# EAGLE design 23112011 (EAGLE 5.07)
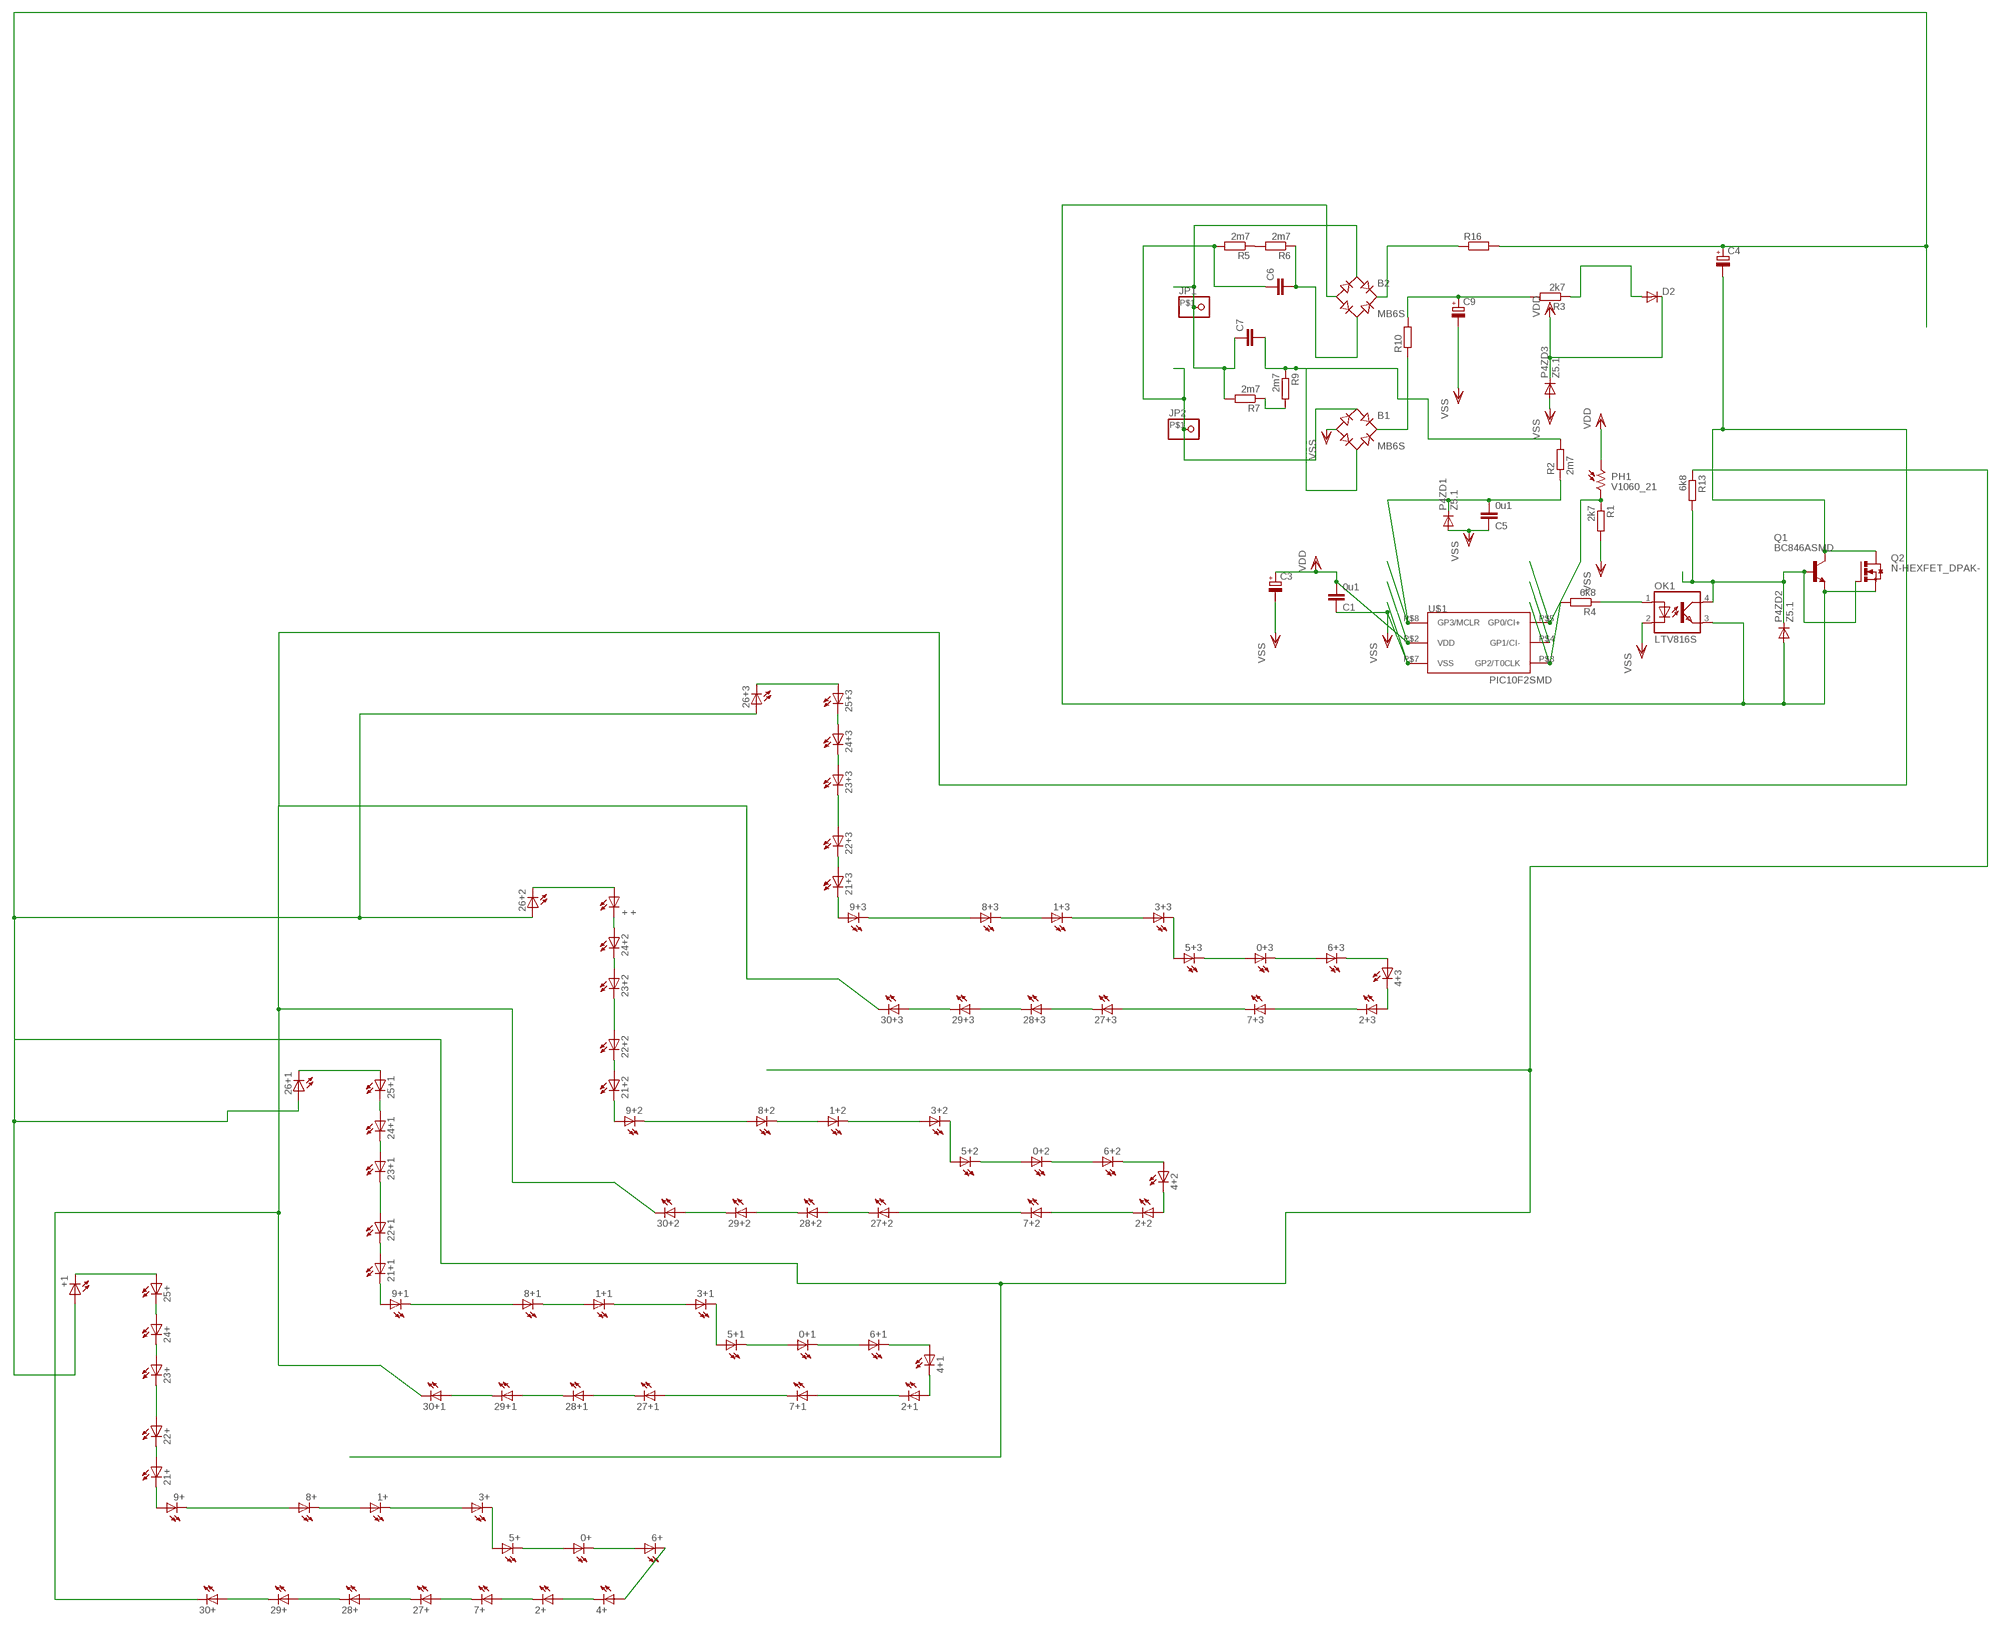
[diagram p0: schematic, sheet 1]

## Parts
0+  LED1210  [1210]
0+1  LED1210  [1210]
0+2  LED1210  [1210]
0+3  LED1210  [1210]
1+  LED1210  [1210]
1+1  LED1210  [1210]
1+2  LED1210  [1210]
1+3  LED1210  [1210]
2+  LED1210  [1210]
2+1  LED1210  [1210]
2+2  LED1210  [1210]
2+3  LED1210  [1210]
3+  LED1210  [1210]
3+1  LED1210  [1210]
3+2  LED1210  [1210]
3+3  LED1210  [1210]
4+  LED1210  [1210]
4+1  LED1210  [1210]
4+2  LED1210  [1210]
4+3  LED1210  [1210]
5+  LED1210  [1210]
5+1  LED1210  [1210]
5+2  LED1210  [1210]
5+3  LED1210  [1210]
6+  LED1210  [1210]
6+1  LED1210  [1210]
6+2  LED1210  [1210]
6+3  LED1210  [1210]
7+  LED1210  [1210]
7+1  LED1210  [1210]
7+2  LED1210  [1210]
7+3  LED1210  [1210]
8+  LED1210  [1210]
8+1  LED1210  [1210]
8+2  LED1210  [1210]
8+3  LED1210  [1210]
9+  LED1210  [1210]
9+1  LED1210  [1210]
9+2  LED1210  [1210]
9+3  LED1210  [1210]
21+  LED1210  [1210]
21+1  LED1210  [1210]
21+2  LED1210  [1210]
21+3  LED1210  [1210]
22+  LED1210  [1210]
22+1  LED1210  [1210]
22+2  LED1210  [1210]
22+3  LED1210  [1210]
23+  LED1210  [1210]
23+1  LED1210  [1210]
23+2  LED1210  [1210]
23+3  LED1210  [1210]
24+  LED1210  [1210]
24+1  LED1210  [1210]
24+2  LED1210  [1210]
24+3  LED1210  [1210]
25+  LED1210  [1210]
25+1  LED1210  [1210]
25+3  LED1210  [1210]
26+1  LED1210  [1210]
26+2  LED1210  [1210]
26+3  LED1210  [1210]
27+  LED1210  [1210]
27+1  LED1210  [1210]
27+2  LED1210  [1210]
27+3  LED1210  [1210]
28+  LED1210  [1210]
28+1  LED1210  [1210]
28+2  LED1210  [1210]
28+3  LED1210  [1210]
29+  LED1210  [1210]
29+1  LED1210  [1210]
29+2  LED1210  [1210]
29+3  LED1210  [1210]
30+  LED1210  [1210]
30+1  LED1210  [1210]
30+2  LED1210  [1210]
30+3  LED1210  [1210]
+  +  LED1210  [1210]
+1  LED1210  [1210]
B1  MB6S  [SOIC-4]
B2  MB6S  [SOIC-4]
C1  0u1  C-EUC1206  [C1206]
C3  CPOL-EUD  [PANASONIC_D]
C4  CPOL-EUSANYO_SMD_F12  [SANYO-OSCON_SMD_F12]
C5  0u1  C-EUC1206  [C1206]
C6  C-EUSMD200  [SMD200]
C7  C-EUSMD100  [SMD100]
C9  CPOL-EUD  [PANASONIC_D]
D2  DIODE-MINIMELF  [MINIMELF]
JP1  PINHD-1X1SMD  [SMD1X1]
JP2  PINHD-1X1SMD  [SMD1X1]
OK1  LTV816S  [SMD4]
P4ZD1  Z5.1  DIODE-MINIMELF  [MINIMELF]
P4ZD2  Z5.1  DIODE-MINIMELF  [MINIMELF]
P4ZD3  Z5.1  DIODE-MINIMELF  [MINIMELF]
PH1  V1060_21  [TO-5_V10]
Q1  BC846ASMD  [SOT23]
Q2  N-HEXFET_DPAK-  [TO252]
R1  2k7  R-EU_R1206  [R1206]
R2  2m7  R-EU_R1206  [R1206]
R3  2k7  R-EU_R1206  [R1206]
R4  6k8  R-EU_R1206  [R1206]
R5  2m7  R-EU_R1210  [R1210]
R6  2m7  R-EU_R1210  [R1210]
R7  2m7  R-EU_R1210  [R1210]
R9  2m7  R-EU_R1210  [R1210]
R10  R-EU_SMD15  [SMDCARB15]
R13  6k8  R-EU_R1206  [R1206]
R16  R-EU_SMD15  [SMDCARB15]
U$1  PIC10F2SMD  [DIL8SMD]

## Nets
AC1: B1.~1(AC1) C6.P$1 JP2.P$1 R5.2
AC2: B2.~1(AC1) C7.P$1 JP1.P$1 R7.2
CBIG: B2.~2(AC2) C6.P$2 R6.1
CSMALL: B1.~2(AC2) C7.P$2 R2.2 R9.1
D+: 26+1.P$1(A) 26+2.P$1(A) 26+3.P$1(A) +1.P$1(A) C4.+ R13.1 R16.P$2
DR+: C9.+ R3.2 R10.P$2
MINUS: 30+1.P$2(C) 30+2.P$2(C) 30+3.P$2(C) 30+.P$2(C) C4.- Q1.3(C) Q2.3(D)
N$6: 8+.P$1(A) 9+.P$2(C)
N$7: 29+.P$2(C) 30+.P$1(A)
N$8: 28+.P$2(C) 29+.P$1(A)
N$9: 27+.P$2(C) 28+.P$1(A)
N$10: 29+1.P$2(C) 30+1.P$1(A)
N$11: 28+1.P$2(C) 29+1.P$1(A)
N$12: 2+.P$2(C) 7+.P$1(A)
N$13: 7+.P$2(C) 27+.P$1(A)
N$14: 2+.P$1(A) 4+.P$2(C)
N$15: 4+.P$1(A) 6+.P$2(C)
N$16: 0+.P$2(C) 6+.P$1(A)
N$17: 0+.P$1(A) 5+.P$2(C)
N$18: 3+.P$2(C) 5+.P$1(A)
N$19: 1+.P$2(C) 3+.P$1(A)
N$20: 1+.P$1(A) 8+.P$2(C)
N$21: 27+1.P$2(C) 28+1.P$1(A)
N$22: 2+1.P$1(A) 4+1.P$2(C)
N$23: 9+.P$1(A) 21+.P$2(C)
N$24: 21+.P$1(A) 22+.P$2(C)
N$25: 22+.P$1(A) 23+.P$2(C)
N$26: 24+.P$1(A) 25+.P$2(C)
N$27: 25+.P$1(A) +1.P$2(C)
N$28: 23+.P$1(A) 24+.P$2(C)
N$29: 4+1.P$1(A) 6+1.P$2(C)
N$30: 0+1.P$2(C) 6+1.P$1(A)
N$31: 0+1.P$1(A) 5+1.P$2(C)
N$32: 3+1.P$2(C) 5+1.P$1(A)
N$33: 1+1.P$2(C) 3+1.P$1(A)
N$34: 1+1.P$1(A) 8+1.P$2(C)
N$35: 9+1.P$1(A) 21+1.P$2(C)
N$36: 21+1.P$1(A) 22+1.P$2(C)
N$37: 22+1.P$1(A) 23+1.P$2(C)
N$38: 25+1.P$1(A) 26+1.P$2(C)
N$39: 24+1.P$1(A) 25+1.P$2(C)
N$40: 23+1.P$1(A) 24+1.P$2(C)
N$41: 2+1.P$2(C) 7+1.P$1(A)
N$42: 7+1.P$2(C) 27+1.P$1(A)
N$43: 8+1.P$1(A) 9+1.P$2(C)
N$46: 29+2.P$2(C) 30+2.P$1(A)
N$47: 28+2.P$2(C) 29+2.P$1(A)
N$48: 27+2.P$2(C) 28+2.P$1(A)
N$49: 2+2.P$1(A) 4+2.P$2(C)
N$50: 4+2.P$1(A) 6+2.P$2(C)
N$51: 0+2.P$2(C) 6+2.P$1(A)
N$52: 0+2.P$1(A) 5+2.P$2(C)
N$53: 3+2.P$2(C) 5+2.P$1(A)
N$54: 1+2.P$2(C) 3+2.P$1(A)
N$55: 1+2.P$1(A) 8+2.P$2(C)
N$56: 9+2.P$1(A) 21+2.P$2(C)
N$57: 21+2.P$1(A) 22+2.P$2(C)
N$58: 22+2.P$1(A) 23+2.P$2(C)
N$59: 26+2.P$2(C) +.P$1(A)
N$60: 24+2.P$1(A) +.P$2(C)
N$61: 23+2.P$1(A) 24+2.P$2(C)
N$62: 2+2.P$2(C) 7+2.P$1(A)
N$63: 7+2.P$2(C) 27+2.P$1(A)
N$64: 8+2.P$1(A) 9+2.P$2(C)
N$67: 29+3.P$2(C) 30+3.P$1(A)
N$68: 28+3.P$2(C) 29+3.P$1(A)
N$69: 27+3.P$2(C) 28+3.P$1(A)
N$70: 2+3.P$1(A) 4+3.P$2(C)
N$71: 4+3.P$1(A) 6+3.P$2(C)
N$72: 0+3.P$2(C) 6+3.P$1(A)
N$73: 0+3.P$1(A) 5+3.P$2(C)
N$74: 3+3.P$2(C) 5+3.P$1(A)
N$75: 1+3.P$2(C) 3+3.P$1(A)
N$76: 1+3.P$1(A) 8+3.P$2(C)
N$77: 9+3.P$1(A) 21+3.P$2(C)
N$78: 21+3.P$1(A) 22+3.P$2(C)
N$79: 22+3.P$1(A) 23+3.P$2(C)
N$80: 25+3.P$1(A) 26+3.P$2(C)
N$81: 24+3.P$1(A) 25+3.P$2(C)
N$82: 23+3.P$1(A) 24+3.P$2(C)
N$83: 2+3.P$2(C) 7+3.P$1(A)
N$84: 7+3.P$2(C) 27+3.P$1(A)
N$85: 8+3.P$1(A) 9+3.P$2(C)
N$86: C5.2 P4ZD1.C R2.1 U$1.P$8(GP3/MCLR)
N$87: OK1.1(A) R4.1
N$88: PH1.2 R1.1 U$1.P$5(GP0/CI+)
N$89: R5.1 R6.2
N$90: R7.1 R9.2
N$91: B2.+ R16.P$1
N$92: D2.A R3.1
N$93: B2.- OK1.3(EMIT) P4ZD2.A Q1.2(E) Q2.2(S)
N$94: OK1.4(COL) P4ZD2.C Q1.1(B) Q2.1(G) R13.2
N$95: R4.2 U$1.P$3(GP2/T0CLK)
N$102: U$1.P$4(GP1/CI-)
RECDR+: B1.+ R10.P$1
VDD: C1.2 C3.+ D2.C P4ZD3.C PH1.1 U$1.P$2(VDD)
VSS: B1.- C1.1 C3.- C5.1 C9.- OK1.2(C) P4ZD1.A P4ZD3.A R1.2 U$1.P$7(VSS)

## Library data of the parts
0+ 0+1-0+3 1+ 1+1-1+3 2+ 2+1-2+3 3+ 3+1-3+3 4+ 4+1-4+3 5+ 5+1-5+3 6+ 6+1-6+3 7+ 7+1-7+3 8+ 8+1-8+3 9+ 9+1-9+3 21+ 21+1-21+3 22+ 22+1-22+3 23+ 23+1-23+3 24+ 24+1-24+3 25+ 25+1 25+3 26+1-26+3 27+ 27+1-27+3 28+ 28+1-28+3 29+ 29+1-29+3 30+ 30+1-30+3 + +1 = led(2):LED: LED
B1 B2 = rectifier:MB*S: Bridge Rectifier Source: http://www.fairchildsemi.com/ds/MB/MB6S.pdf
C1 C5-C7 = rcl:C-EU: CAPACITOR, European symbol
C3 C4 C9 = rcl-2:CPOL-EU: POLARIZED CAPACITOR, European symbol
D2 P4ZD1-P4ZD3 = diode:DIODE-: DIODE
JP1 JP2 = pinhead:PINHD-1X1: PIN HEADER
OK1 = optocoupler:LTV816: OPTO COUPLER Source: LITEON, LTV816.pdf
PH1 = photo-elements:?1060*: Sensor Street Light control
Q1 = transistor-npn:BC846*: NPN Transistor
Q2 = transistor-power:N-HEXFET_?-*: HEXFET® Power MOSFET
R1-R7 R9 R13 = rcl-2:R-EU_: RESISTOR, European symbol
R10 R16 = rcl:R-EU_: RESISTOR, European symbol
U$1 = microchip-5:PIC10F2*: uPC nW 0,25/0,5k Program Flash memory Comparator

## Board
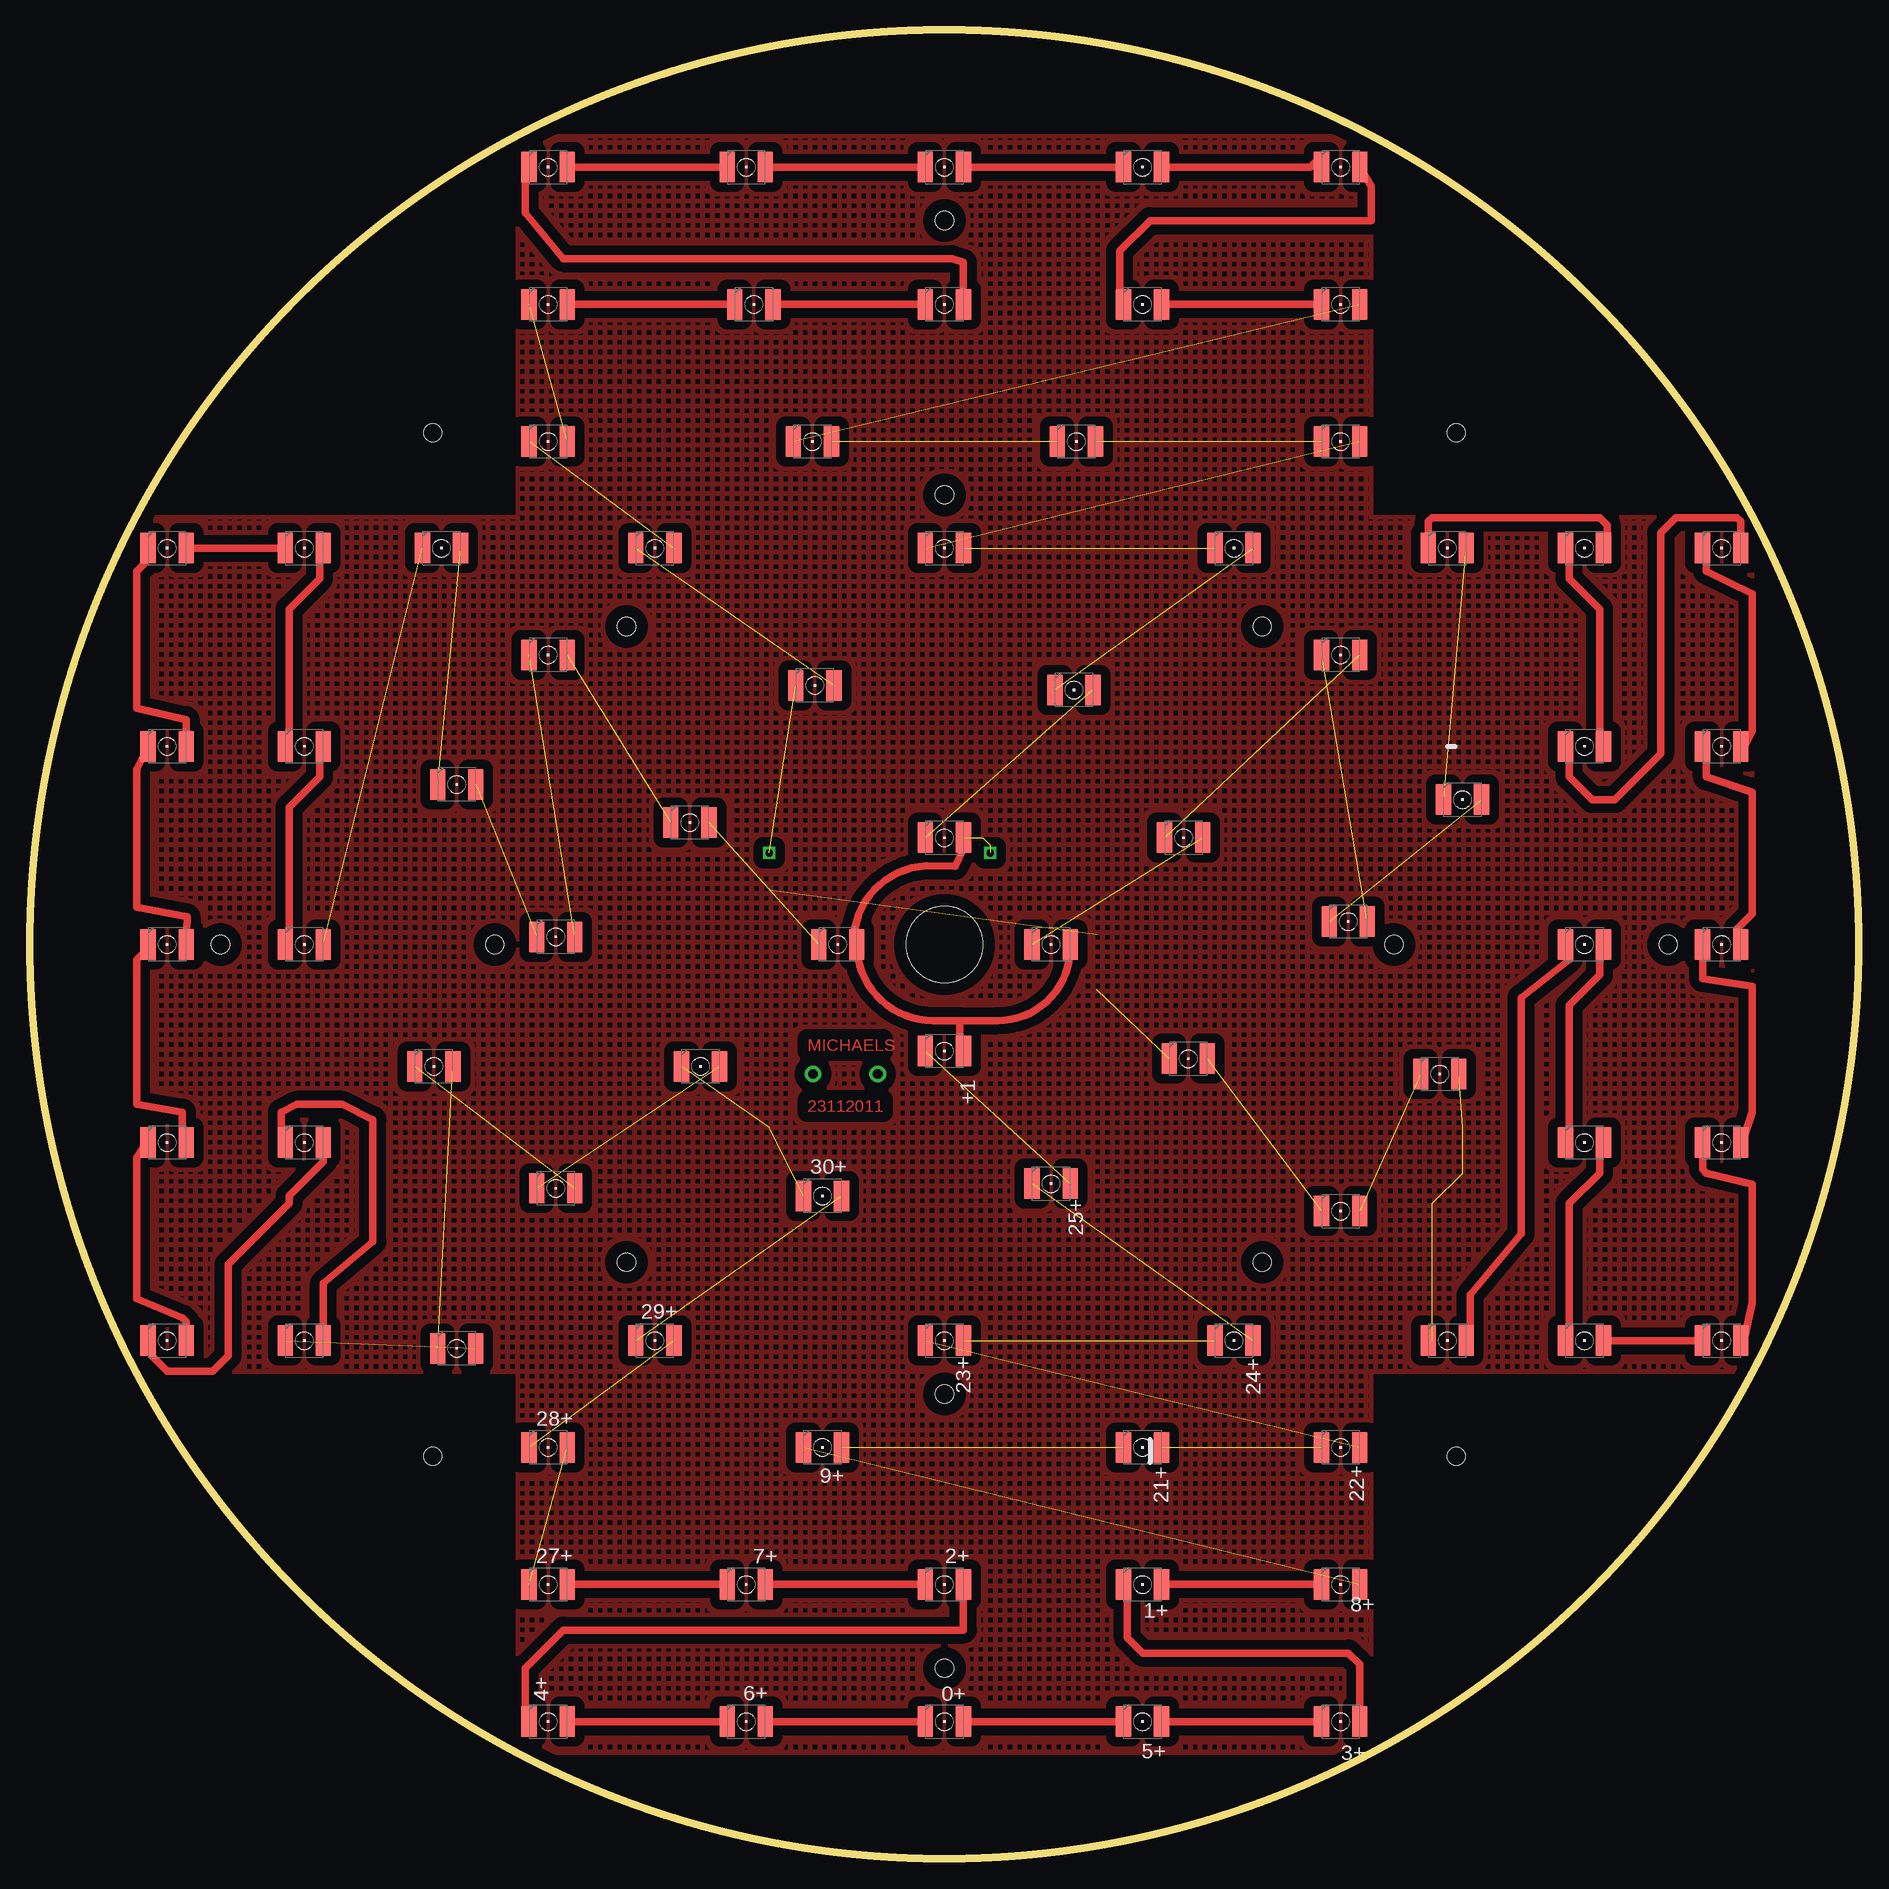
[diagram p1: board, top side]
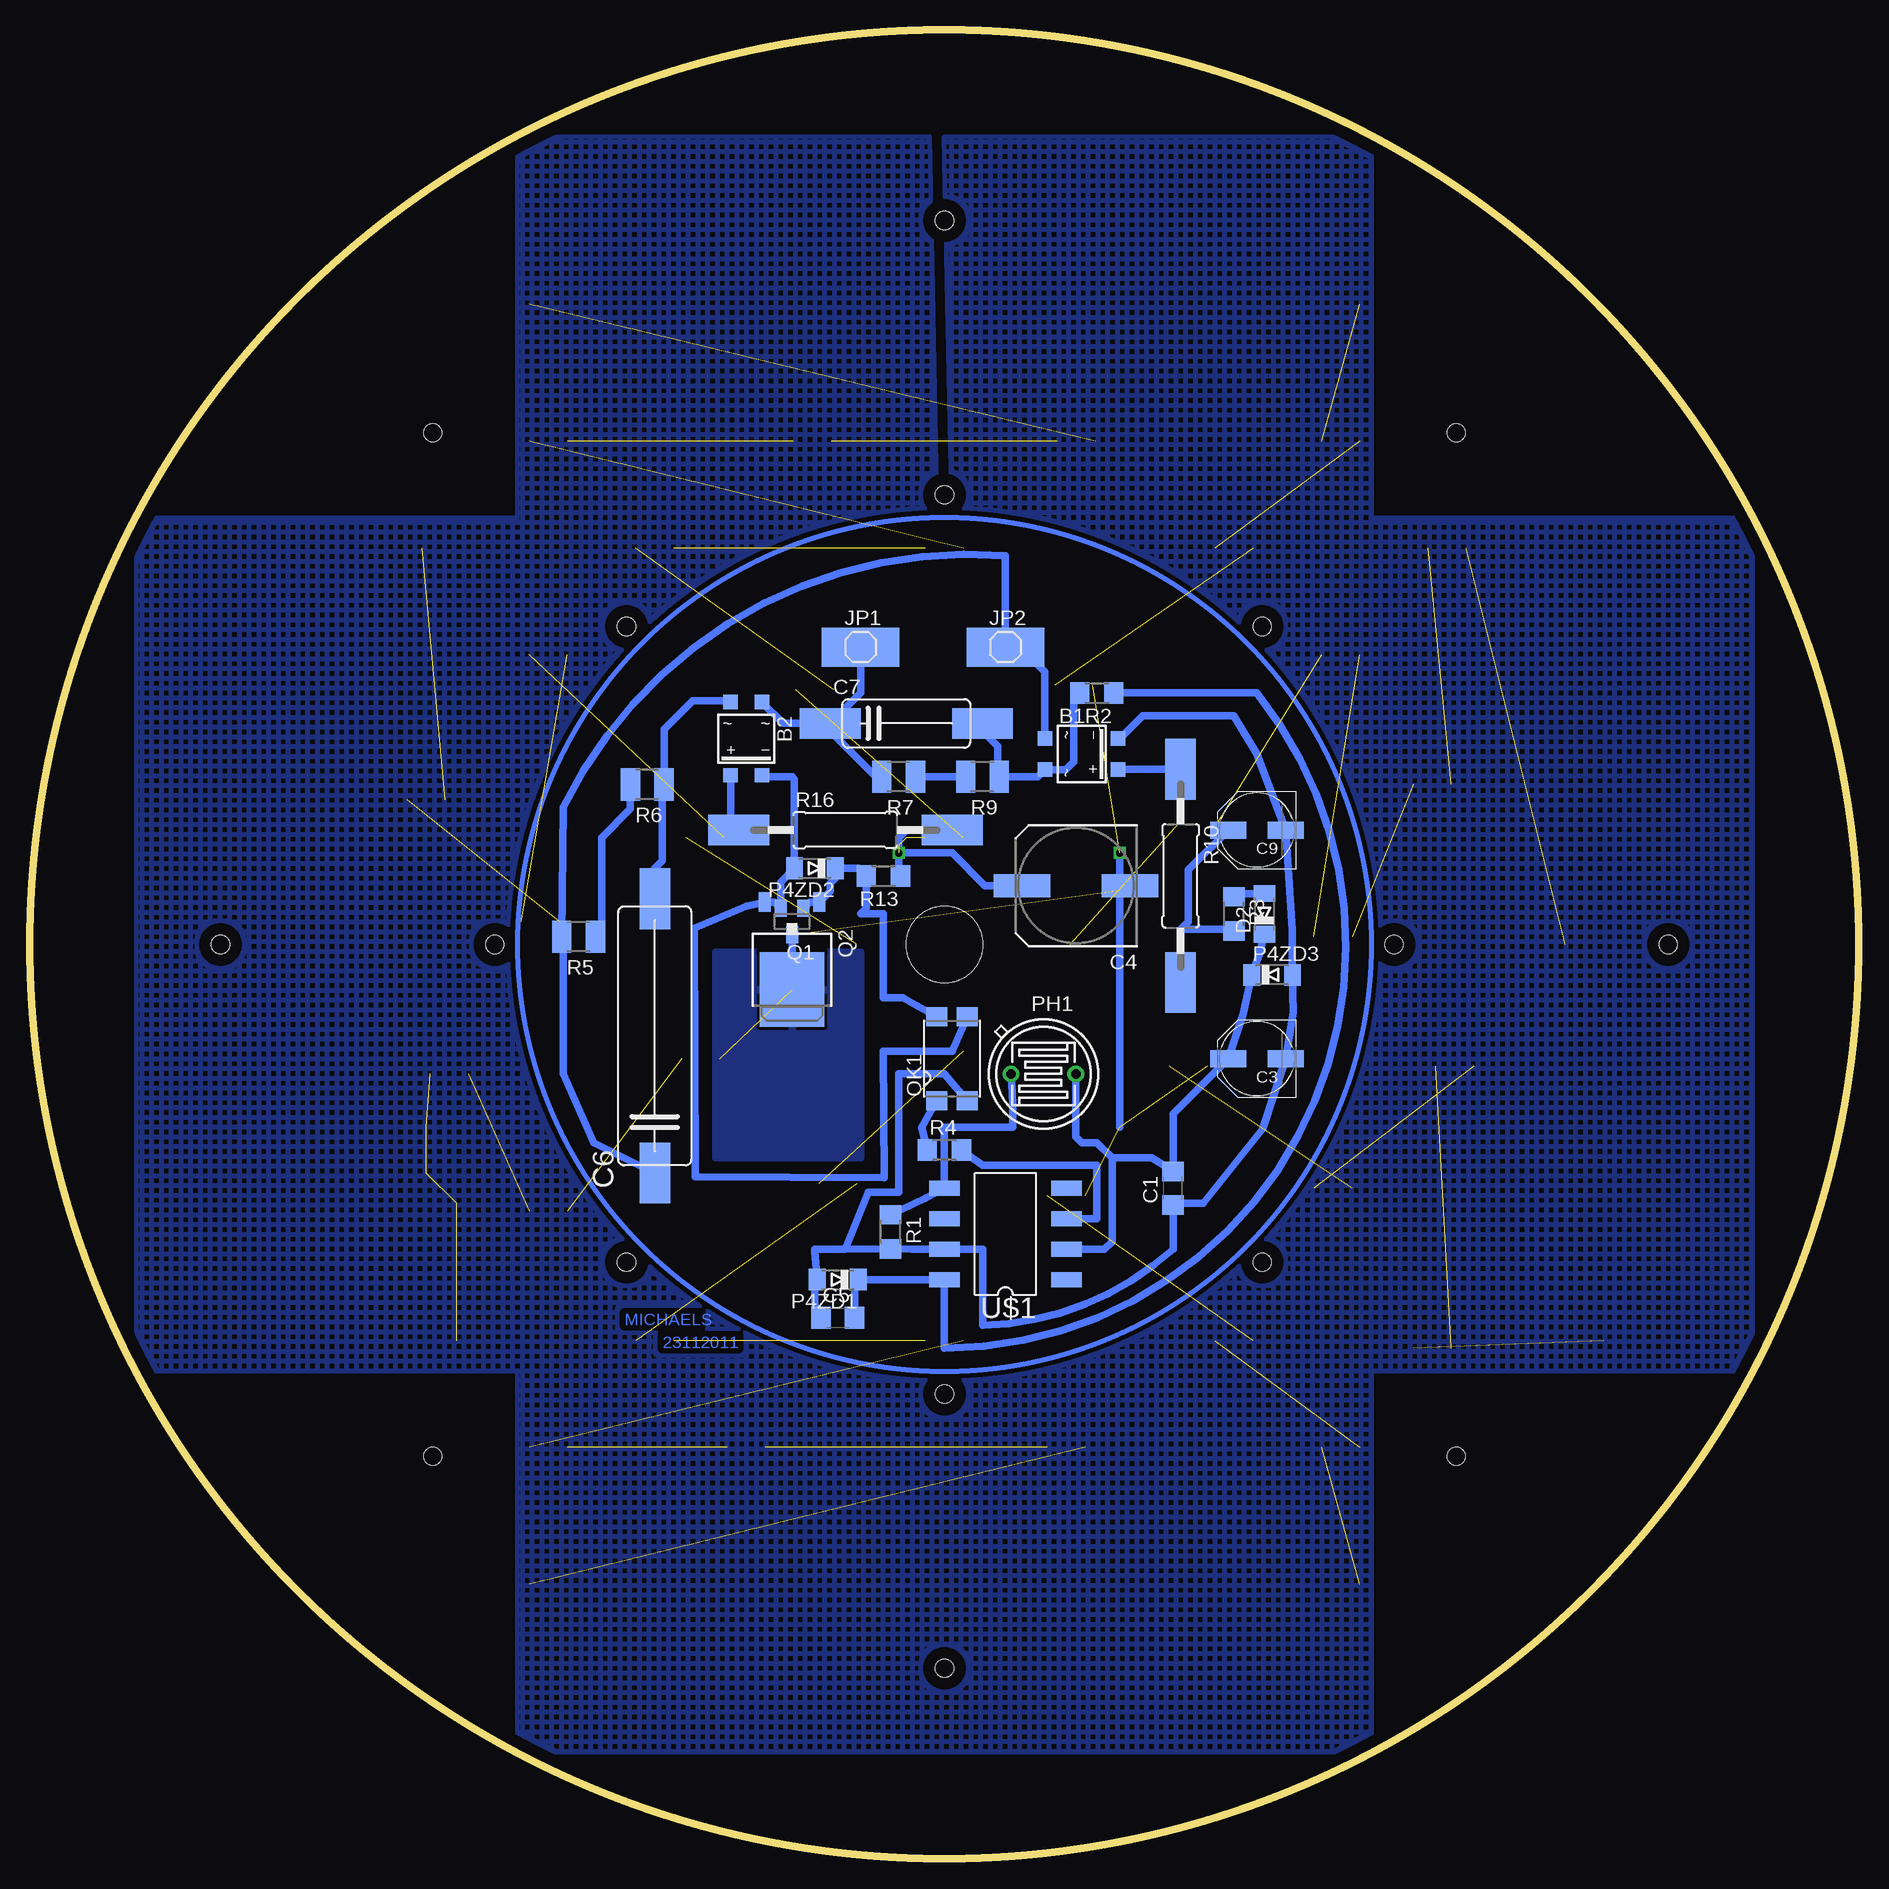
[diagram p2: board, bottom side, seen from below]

Size 152.4 x 152.4 mm. Coordinates in mm from the lower left corner, seen from the top.
Outline: circle at 76.2,76.2 radius 76.2
Copper layers (1*16): Top 0.035mm / dielectric 1.5mm / Bottom 0.035mm
Design rules "default": minimum track width 10mil, minimum drill 24mil, track to track 8mil, track to pad 8mil, pad to pad 8mil, via to via 8mil, smd to smd 8mil, copper to edge 40mil, drill to drill 8mil, minimum pad ring 10mil, minimum via ring 8mil, stop-mask expansion 4mil, vias tented up to drill 0mil, thermal gap 10mil
Holes 6.35 mm at 76.2,76.2
Holes 1.5 mm at 136.53,76.2 118.85,33.55 118.85,118.85 33.55,118.85 76.2,136.53 15.88,76.2 33.55,33.55 76.2,15.88 76.2,38.73 76.2,113.67 113.67,76.2 38.73,76.2 49.71,102.69 102.69,102.69 102.69,49.71 49.71,49.71

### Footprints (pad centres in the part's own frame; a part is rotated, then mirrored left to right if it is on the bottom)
1210 = smd 1.27 x 2.54: P$1 1.587,0; P$2 -1.587,0
SOIC-4 = smd 1.2 x 1.2: + 1.3,3.05; - -1.3,3.05; ~1 -1.3,-3.05; ~2 1.3,-3.05
C1206 = smd 1.6 x 1.8: 1 -1.4,0; 2 1.4,0
PANASONIC_D = smd 3 x 1.4: + 2.4,0; - -2.4,0
SANYO-OSCON_SMD_F12 = smd 4.7 x 1.9: + 4.5,0; - -4.5,0
SMD200 = smd 5.08 x 2.54: P$1 -10.16,0; P$2 12.7,0
SMD100 = smd 5.08 x 2.54: P$1 -6.35,0; P$2 6.35,0
MINIMELF = smd 1.4 x 1.8: A 1.7,0; C -1.7,0
SMD1X1 = smd 6.452 x 3.251: P$1 0,0
SMD4 = smd 1.78 x 1.55: 1 -1.27,-3.5; 2 1.27,-3.5; 3 1.27,3.5; 4 -1.27,3.5
TO-5_V10 = drill 0.8 pad 1.4 round: 1 -2.7,0; 2 2.7,0
SOT23 = smd 1 x 1.4: 1 -0.95,-1.1; 2 0.95,-1.1; 3 0,1.1
TO252 = smd 1 x 1.6: 1 -2.28,-3.53; 2 2.28,-3.53 | smd 5.4 x 6.2: 3 0,3.77
R1206 = smd 1.6 x 1.803: 1 -1.422,0; 2 1.422,0
R1210 = smd 1.6 x 2.7: 1 -1.4,0; 2 1.4,0
SMDCARB15 = smd 5.08 x 2.54: P$1 -8.89,0; P$2 8.89,0
DIL8SMD = smd 1.27 x 2.54: P$1 -3.81,-5.08; P$2 -1.27,-5.08; P$3 1.27,-5.08; P$4 3.81,-5.08; P$5 3.81,5.08; P$6 1.27,5.08; P$7 -1.27,5.08; P$8 -3.81,5.08

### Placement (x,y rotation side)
0+  76.2,11.43 0 top
0+1  140.97,59.69 0 top
0+2  76.2,140.97 0 top
0+3  11.43,76.2 0 top
1+  92.71,22.86 0 top
1+1  140.97,109.22 0 top
1+2  92.71,129.54 0 top
1+3  22.86,109.22 0 top
2+  76.2,22.86 0 top
2+1  129.54,59.69 0 top
2+2  76.2,129.54 0 top
2+3  22.86,59.69 0 top
3+  109.22,11.43 0 top
3+1  140.97,92.71 0 top
3+2  109.22,140.97 0 top
3+3  11.43,109.22 0 top
4+  43.18,11.43 0 top
4+1  129.54,43.18 0 top
4+2  43.18,140.97 0 top
4+3  11.43,43.18 0 top
5+  92.71,11.43 0 top
5+1  140.97,76.2 0 top
5+2  92.71,140.97 0 top
5+3  11.43,92.71 0 top
6+  59.69,11.43 0 top
6+1  140.97,43.18 0 top
6+2  59.69,140.97 0 top
6+3  11.43,59.69 0 top
7+  59.69,22.86 0 top
7+1  129.54,76.2 0 top
7+2  60.33,129.54 0 top
7+3  22.86,43.18 0 top
8+  109.22,22.86 0 top
8+1  129.54,92.71 0 top
8+2  109.22,129.54 0 top
8+3  22.86,92.71 0 top
9+  66.04,34.29 0 top
9+1  129.54,109.22 0 top
9+2  65.2,118.11 0 top
9+3  22.86,76.2 0 top
21+  92.71,34.29 0 top
21+1  118.11,109.22 0 top
21+2  87.2,118.11 0 top
21+3  34.29,109.22 0 top
22+  109.22,34.29 0 top
22+1  119.38,88.27 0 top
22+2  109.22,118.11 0 top
22+3  35.56,89.53 0 top
23+  76.2,43.18 0 top
23+1  109.86,78.11 0 top
23+2  76.2,109.22 0 top
23+3  43.81,76.83 0 top
24+  100.33,43.18 0 top
24+1  109.22,100.33 0 top
24+2  100.33,109.22 0 top
24+3  43.18,100.33 0 top
25+  85.09,56.26 0 top
25+1  96.14,85.09 0 top
25+3  54.99,86.36 0 top
26+1  85.09,76.2 0 top
26+2  76.2,85.09 0 top
26+3  67.31,76.2 0 top
27+  43.18,22.86 0 top
27+1  118.11,43.18 0 top
27+2  43.18,129.54 0 top
27+3  35.56,42.55 0 top
28+  43.18,34.29 0 top
28+1  117.47,65.41 0 top
28+2  43.18,118.11 0 top
28+3  33.66,66.04 0 top
29+  52.07,43.18 0 top
29+1  109.22,53.98 0 top
29+2  52.07,109.22 0 top
29+3  43.81,55.88 0 top
30+  66.04,55.24 0 top
30+1  96.52,66.67 0 top
30+2  65.41,97.79 0 top
30+3  55.88,66.04 0 top
+  87,97.41 0 top
+1  76.2,67.31 0 top
B1  64.77,92.08 270 bottom
B2  92.71,93.34 180 bottom
C1  57.15,55.88 90 bottom
C3  50.16,66.67 180 bottom
C4  65.22,81.09 180 bottom
C5  85.09,45.09 0 bottom
C6  100.33,67.31 90 bottom
C7  79.38,94.61 0 bottom
C9  50.16,85.72 180 bottom
D2  49.53,78.74 90 bottom
JP1  83.19,100.97 0 bottom
JP2  71.12,100.97 0 bottom
OK1  75.56,66.67 0 bottom
P4ZD1  85.09,48.26 180 bottom
P4ZD2  87,82.55 180 bottom
P4ZD3  48.9,73.66 0 bottom
PH1  67.94,65.41 180 bottom
Q1  88.9,78.11 180 bottom
Q2  88.9,76.2 180 bottom
R1  80.69,52.24 270 bottom
R2  63.5,97.16 180 bottom
R3  52.07,78.74 270 bottom
R4  76.2,59.05 0 bottom
R5  106.68,76.83 180 bottom
R6  100.97,89.53 180 bottom
R7  80.01,90.17 180 bottom
R9  73.03,90.17 180 bottom
R10  56.52,81.92 270 bottom
R13  81.28,81.92 180 bottom
R16  84.45,85.72 0 bottom
U$1  71.12,52.07 90 bottom

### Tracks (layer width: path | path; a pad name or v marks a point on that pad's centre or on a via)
AC1
  Bottom 0.61: B1.~1 67.82,98.94 69.85,100.97 JP2.P$1 71.12,108.58 arc-69 107.95,87.63 R5.2 107.95,76.7 107.95,65.41 105.41,59.69 C6.P$1
AC2
  Bottom 0.61: R7.2 81.92,90.17 86.36,94.61 C7.P$1 | JP1.P$1 83.19,97.16 C7.P$1 | C7.P$1 89.63,94.61 B2.~1
CBIG
  Bottom 0.61: B2.~2 94.14,96.52 97.16,96.52 99.56,94.11 R6.1 99.69,89.41 99.69,83.19 100.33,82.55 C6.P$2
CSMALL
  Bottom 0.61: R2.2 65.41,96.67 65.41,91.44 66.07,90.78 B1.~2 68.42,90.17 R9.1 71.75,90.3 71.75,92.71 73.03,93.98 C7.P$2
D+  (via drill 0.6)  (3 unrouted)
  Top 0.61: 26+2.P$1 77.79,84.14 77.09,82.71 74.68,82.75 arc77 68.74,77.55 69.22,76.52 26+3.P$1 arc90 75.25,69.85 77.47,69.85 | +1.P$1 77.47,67.63 77.47,69.85 | 26+1.P$1 86.68,75.88 arc-90 80.64,69.85 77.47,69.85
  Bottom 0.61: R13.1 80.01,81.92 v80.01,83.82 | C4.+ 72.84,81.09 75.56,83.82 v80.01,83.82 | R16.P$2 79.38,85.72 80.01,85.09 v80.01,83.82
DR+
  Bottom 0.61: C9.+ 55.88,82.41 55.88,78.11 56.52,77.47 | R10.P$2 56.52,77.47 | R3.2 52.22,77.47 56.52,77.47
MINUS  (via drill 0.6)  (5 unrouted)
  Bottom 0.61: Q2.3 Q1.3 | v61.59,83.82 61.59,81.33 C4.- 61.59,80.7 61.59,60.96
  pour Bottom: 83.82,75.56 95.25,75.56 95.25,74.3 95.25,58.42 83.19,58.42 83.19,75.56
N$1
  pour Bottom (isolate 0.406, hatched): 76.2,143.51 40.64,143.51 40.64,111.76 8.89,111.76 8.89,40.64 40.64,40.64 40.64,8.89 111.76,8.89 111.76,40.64 143.51,40.64 143.51,111.76 111.76,111.76 111.76,143.51 77.47,143.51 76.83,111.76 arc-57 104.14,98.42 arc-48 111.76,76.83 arc-40 105.41,55.88 arc-44 89.53,43.18 arc-54 62.87,43.18 arc-45 45.72,57.78 arc-62 42.55,87.63 arc-49 53.34,103.5 arc-50 75.56,111.76
N$3
  pour Top (isolate 0.813, hatched): 8.89,40.64 40.64,40.64 40.64,8.89 111.76,8.89 111.76,40.64 143.51,40.64 143.51,111.76 111.76,111.76 111.76,143.51 40.64,143.51 40.64,111.76 8.89,111.76
N$6  (1 unrouted)
N$7  (1 unrouted)
N$8  (1 unrouted)
N$9  (1 unrouted)
N$10  (1 unrouted)
N$11  (1 unrouted)
N$12
  Top 0.61: 7+.P$1 2+.P$2
N$13
  Top 0.61: 27+.P$1 7+.P$2
N$14
  Top 0.61: 2+.P$1 77.79,19.05 44.45,19.05 41.27,15.88 41.27,11.75 4+.P$2
N$15
  Top 0.61: 4+.P$1 6+.P$2
N$16
  Top 0.61: 6+.P$1 0+.P$2
N$17
  Top 0.61: 0+.P$1 5+.P$2
N$18
  Top 0.61: 5+.P$1 3+.P$2
N$19
  Top 0.61: 3+.P$1 110.81,16.19 109.86,17.14 92.71,17.14 91.44,18.41 91.44,22.54 1+.P$2
N$20
  Top 0.61: 1+.P$1 8+.P$2
N$21  (4 unrouted)
  Top 0.61: 27+1.P$2 116.84,43.18
N$22
  Top 0.61: 4+1.P$2 128.27,43.18 128.27,54.61 130.81,57.15 130.81,59.69 2+1.P$1
N$23  (1 unrouted)
N$24  (1 unrouted)
N$25  (1 unrouted)
N$26  (1 unrouted)
N$27  (1 unrouted)
N$28  (1 unrouted)
N$29
  Top 0.61: 4+1.P$1 6+1.P$2
N$30
  Top 0.61: 0+1.P$2 139.38,57.47 139.7,57.15 143.51,56.2 143.51,46.35 142.88,43.5 6+1.P$1
N$31
  Top 0.61: 5+1.P$2 139.38,73.34 143.51,72.7 143.51,62.23 142.88,60.33 142.88,60.01 0+1.P$1
N$32
  Top 0.61: 142.88,76.2 5+1.P$1 142.24,76.52 142.24,77.47 143.51,78.74 143.51,88.9 139.7,90.17 139.7,92.71 3+1.P$2
N$33
  Top 0.61: 3+1.P$1 142.88,92.71 143.51,93.98 143.51,105.41 139.7,107.31 139.7,109.22 1+1.P$2
N$34
  Top 0.61: 1+1.P$1 142.56,111.44 142.24,111.76 137.16,111.76 135.89,110.49 135.89,92.08 132.08,88.27 130.18,88.27 128.27,90.17 128.27,92.39 8+1.P$2
N$35
  Top 0.61: 21+1.P$2 116.52,111.44 116.84,111.76 130.81,111.76 131.44,111.12 131.44,109.54 9+1.P$1
N$36  (1 unrouted)
N$37  (1 unrouted)
N$38  (1 unrouted)
N$39  (1 unrouted)
N$40  (1 unrouted)
N$41
  Top 0.61: 2+1.P$2 128.27,59.69 128.27,71.12 130.81,73.66 130.81,76.2 7+1.P$1
N$42
  Top 0.61: 27+1.P$1 120.02,43.18 120.02,46.99 124.27,52.07 124.27,71.75 128.27,74.93 128.27,76.2 7+1.P$2
N$43
  Top 0.61: 8+1.P$1 130.81,92.71 130.81,104.14 128.27,106.68 128.27,109.22 9+1.P$2
N$46  (1 unrouted)
N$47  (1 unrouted)
N$48  (1 unrouted)
N$49
  Top 0.61: 2+2.P$1 77.79,133.03 76.83,133.35 44.45,133.35 41.27,137.16 41.27,140.65 4+2.P$2
N$50
  Top 0.61: 4+2.P$1 6+2.P$2
N$51
  Top 0.61: 6+2.P$1 0+2.P$2
N$52
  Top 0.61: 0+2.P$1 5+2.P$2
N$53
  Top 0.61: 5+2.P$1 106.68,140.97 107.31,141.6 3+2.P$2
N$54
  Top 0.61: 3+2.P$1 111.76,139.38 111.76,136.53 93.34,136.53 90.81,133.99 90.81,129.86 1+2.P$2
N$55
  Top 0.61: 1+2.P$1 8+2.P$2
N$56  (1 unrouted)
N$57  (1 unrouted)
N$58  (1 unrouted)
N$59  (1 unrouted)
N$60  (1 unrouted)
N$61  (1 unrouted)
N$62
  Top 0.61: 7+2.P$1 2+2.P$2
N$63
  Top 0.61: 27+2.P$1 7+2.P$2
N$64  (1 unrouted)
N$67  (1 unrouted)
N$68  (1 unrouted)
N$69  (1 unrouted)
N$70
  Top 0.61: 2+3.P$1 24.45,58.1 21.59,55.24 21.59,54.61 16.51,49.53 16.51,41.91 15.24,40.64 11.43,40.64 10.16,41.91 10.16,42.86 4+3.P$2
N$71
  Top 0.61: 4+3.P$1 13.02,44.77 12.7,45.09 8.89,46.67 8.89,58.42 9.53,59.37 6+3.P$2
N$72
  Top 0.61: 6+3.P$1 12.7,59.69 12.7,62.23 8.89,62.87 8.89,74.93 9.53,75.56 9.53,76.2 0+3.P$2
N$73
  Top 0.61: 0+3.P$1 13.09,78.5 8.89,79.29 8.89,90.81 5+3.P$2
N$74
  Top 0.61: 5+3.P$1 13.02,94.93 8.89,95.89 8.89,107.31 10.16,108.58 10.16,108.9 3+3.P$2
N$75
  Top 0.61: 3+3.P$1 1+3.P$2
N$76
  Top 0.61: 8+3.P$2 21.59,92.71 21.59,104.14 24.13,106.68 24.13,109.22 1+3.P$1
N$77  (1 unrouted)
N$78  (1 unrouted)
N$79  (1 unrouted)
N$80  (1 unrouted)
N$81  (1 unrouted)
N$82  (1 unrouted)
N$83
  Top 0.61: 7+3.P$1 24.45,47.94 28.57,51.44 28.57,61.59 26.04,62.87 22.23,62.87 20.95,62.23 20.95,59.69 2+3.P$2
N$84  (1 unrouted)
N$85
  Top 0.61: 9+3.P$2 21.59,76.2 21.59,87.63 24.13,90.17 24.13,92.71 8+3.P$1
N$86
  Bottom 0.61: R2.1 50.16,97.16 arc129 76.2,42.55 U$1.P$8 P4ZD1.C 83.69,47.96 C5.2
N$87
  Bottom 0.61: OK1.1 78.11,60.96 R4.1
N$88
  Bottom 0.61: R1.1 77.81,55.06 U$1.P$5 76.2,60.96 70.48,60.96 70.48,62.87 PH1.2
N$89
  Bottom 0.61: R5.1 104.78,77.34 104.78,85.09 102.36,87.5 R6.2
N$90
  Bottom 0.61: R9.2 R7.1
N$91
  Bottom 0.61: B2.+ 94.01,86.39 R16.P$1
N$92
  Bottom 0.61: R3.1 51.79,80.44 D2.A
N$93
  Bottom 0.61: OK1.3 75.56,67.31 81.28,67.31 81.22,56.77 96.97,56.84 97.03,77.54 92.71,79.38 Q2.2 90.38,79.73 Q1.2 89.85,81.39 P4ZD2.A 88.69,89.97 88.9,90.17 91.28,90.17 B2.-
N$94
  Bottom 0.61: OK1.4 79.69,71.75 81.28,71.75 81.28,78.74 83.19,78.74 82.7,79.22 R13.2 83.34,82.55 P4ZD2.C 85.3,81.71 85.72,81.28 85.72,80.62 Q2.1 87.42,79.73 Q1.1
N$95
  Bottom 0.61: U$1.P$3 63.5,53.34 63.5,57.78 73.03,57.78 R4.2
RECDR+
  Bottom 0.61: B1.+ 61.69,90.81 R10.P$1
VDD
  Bottom 0.61: D2.C 49.96,75.34 P4ZD3.C 51.3,70.42 C3.+ 57.15,62.09 C1.2 58.92,58.42 62.23,58.42 | 62.23,58.42 63.5,59.69 64.77,59.69 65.25,60.16 PH1.1 | U$1.P$2 62.87,50.8 62.23,51.44 62.23,58.42
VSS
  Bottom 0.61: C5.1 87,46.23 87,47.62 86.79,47.83 P4ZD1.A 87,50.59 87,50.8 84.45,50.8 | B1.- 61.56,93.38 59.69,95.25 52.07,95.25 50.16,92.08 C9.- 47.2,77.41 P4ZD3.A 47.13,70.55 C3.- 49.67,60.82 54.61,54.61 57.02,54.61 C1.1 57.15,50.8 arc41 73.03,44.45 73.03,50.8 U$1.P$7 78.89,50.8 R1.2 84.45,50.8 | 84.45,50.8 82.55,55.56 80.01,55.56 80.01,65.41 76.2,65.41 OK1.2
(copper drawn outside any net)
  shapes: Bottom circle x1

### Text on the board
Top: MICHAELS | 23112011
Bottom: MICHAELS | 23112011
